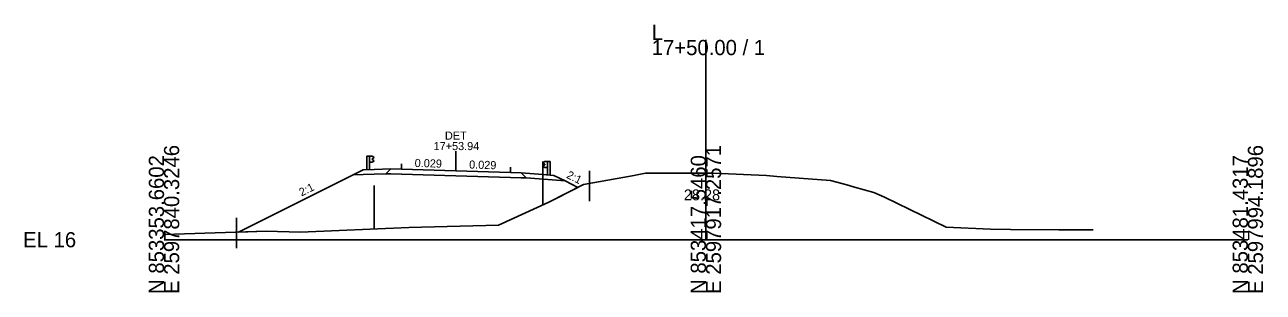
# Model space of a CAD drawing. Extents: x -26 to 1203, y -10 to 9526.
# Drawn here: x -25.7 to 202.8, y 7490.3 to 7539.7 of the extents above; entities that cross this region are included whole.
import ezdxf

# ---------------------------------------------------------------- set-up
doc = ezdxf.new("R2010")
doc.units = 0
for name, color, linetype in [('Exist Cross Section Cell', 7, 'Continuous'), ('Exist XS Center Line Elevation Label', 7, 'Continuous'), ('Exist XS Ground Line', 7, 'Continuous'), ('Prop XS Alignment Label', 7, 'Continuous'), ('Prop XS Earthwork Shape', 7, 'Continuous'), ('Prop XS EOT Tick Mark', 7, 'Continuous'), ('Prop XS Exc Vertical Line 1', 7, 'Continuous'), ('Prop XS Exc Vertical Line 2', 7, 'Continuous'), ('Prop XS Finish Grade', 7, 'Continuous'), ('Prop XS Finish Grade Earthwork', 7, 'Continuous'), ('Prop XS Finish Grade Paved Shoulder', 7, 'Continuous'), ('Prop XS Finish Grade Pavement', 7, 'Continuous'), ('Prop XS Guardrail', 7, 'Continuous'), ('Prop XS Pvmt Edge Slope', 7, 'Continuous'), ('Prop XS SE Text', 7, 'Continuous'), ('Prop XS Side Slope Text', 7, 'Continuous'), ('Prop XS Station Labels', 7, 'Continuous'), ('Prop XS Subgrade Earthwork', 7, 'Continuous'), ('Scratch_Level_1', 7, 'Continuous'), ('Scratch_Level_2', 7, 'Continuous')]:
    doc.layers.add(name, color=color, linetype=linetype)

msp = doc.modelspace()

# ---------------------------------------------------------------- linework, layer by layer
at = {"layer": 'Exist Cross Section Cell'}
for p, q in [((100, 7500), (100, 7536.86)), ((0, 7500), (100, 7500)), ((100, 7500), (200, 7500))]:
    msp.add_line(p, q, dxfattribs=at)
at = {"layer": 'Exist XS Ground Line'}
for p, q in [((86.37, 7511.81), (88.83, 7512.28)), ((88.83, 7512.28), (89.98, 7512.29)), ((89.98, 7512.29), (100.2, 7512.28)), ((100.2, 7512.28), (101.34, 7512.25)), ((101.34, 7512.25), (111.17, 7511.85)), ((71.02, 7506.9), (77.38, 7510.19)), ((77.38, 7510.19), (86.37, 7511.81)), ((111.17, 7511.85), (113.1, 7511.68)), ((113.1, 7511.68), (117.21, 7511.35)), ((117.21, 7511.35), (123.01, 7510.9)), ((123.01, 7510.9), (126.01, 7510.14)), ((126.01, 7510.14), (127.39, 7509.7)), ((127.39, 7509.7), (130.97, 7508.72)), ((130.97, 7508.72), (132.96, 7507.87)), ((132.96, 7507.87), (144.33, 7502.3)), ((61.72, 7502.71), (71.02, 7506.9)), ((0, 7500.98), (18.83, 7501.55)), ((18.83, 7501.55), (25.19, 7501.41)), ((25.19, 7501.41), (45.15, 7502.26)), ((45.15, 7502.26), (61.72, 7502.71)), ((144.33, 7502.3), (152.53, 7501.97)), ((152.53, 7501.97), (156.23, 7501.89)), ((156.23, 7501.89), (165.12, 7501.83)), ((165.12, 7501.83), (171.46, 7501.8))]:
    msp.add_line(p, q, dxfattribs=at)
at = {"layer": 'Prop XS Earthwork Shape'}
msp.add_lwpolyline([(53.87, 7511.79), (43.83, 7512.09), (41.83, 7512.15), (40.94, 7512.17), (38.76, 7512.11), (36.76, 7512.05), (34.92, 7511.99), (13.74, 7501.4), (18.83, 7501.55), (25.19, 7501.41), (45.15, 7502.26), (61.72, 7502.71), (71.02, 7506.9), (76.36, 7509.66), (74, 7510.84), (66.86, 7511.41), (65.92, 7511.44), (63.92, 7511.5)], close=True, dxfattribs=at)
at = {"layer": 'Prop XS EOT Tick Mark'}
for p, q in [((43.83, 7513.01), (43.83, 7514.01)), ((63.92, 7512.41), (63.92, 7513.41))]:
    msp.add_line(p, q, dxfattribs=at)
at = {"layer": 'Prop XS Exc Vertical Line 1'}
msp.add_line((13.38, 7504.04), (13.38, 7498.46), dxfattribs=at)
at = {"layer": 'Prop XS Exc Vertical Line 2'}
msp.add_line((78.51, 7512.73), (78.51, 7507.1), dxfattribs=at)
at = {"layer": 'Prop XS Finish Grade'}
for p, q in [((36.76, 7512.91), (34.92, 7511.99)), ((38.76, 7512.97), (36.76, 7512.91)), ((41.83, 7513.06), (38.76, 7512.97)), ((65.92, 7512.36), (69.93, 7512.03)), ((69.93, 7512.03), (71.93, 7511.87)), ((71.93, 7511.87), (74, 7510.84))]:
    msp.add_line(p, q, dxfattribs=at)
at = {"layer": 'Prop XS Finish Grade Earthwork'}
for p, q in [((34.92, 7511.99), (13.74, 7501.4)), ((74, 7510.84), (76.36, 7509.66))]:
    msp.add_line(p, q, dxfattribs=at)
at = {"layer": 'Prop XS Finish Grade Paved Shoulder'}
for p, q in [((43.83, 7513.01), (41.83, 7513.06)), ((63.92, 7512.41), (65.92, 7512.36))]:
    msp.add_line(p, q, dxfattribs=at)
at = {"layer": 'Prop XS Finish Grade Pavement'}
for p, q in [((43.83, 7513.01), (53.87, 7512.71)), ((53.87, 7512.71), (63.92, 7512.41))]:
    msp.add_line(p, q, dxfattribs=at)
at = {"layer": 'Prop XS Guardrail'}
for p, q in [((37.44, 7515.43), (37.94, 7515.43)), ((37.44, 7512.93), (37.44, 7515.43)), ((37.94, 7515.43), (38.44, 7515.43)), ((37.94, 7515.43), (37.94, 7512.93)), ((38.44, 7514.3), (37.94, 7514.3)), ((38.44, 7515.43), (38.73, 7515.23)), ((38.73, 7515.11), (38.44, 7514.91)), ((38.44, 7514.91), (38.44, 7514.82)), ((38.44, 7514.82), (38.73, 7514.62)), ((38.73, 7514.5), (38.44, 7514.3)), ((38.73, 7515.23), (38.76, 7515.17)), ((38.76, 7515.17), (38.73, 7515.11)), ((38.73, 7514.62), (38.76, 7514.56)), ((38.76, 7514.56), (38.73, 7514.5)), ((69.96, 7514.23), (69.93, 7514.17)), ((69.93, 7514.17), (69.96, 7514.11)), ((70.25, 7514.43), (69.96, 7514.23)), ((70.75, 7514.43), (70.25, 7514.43)), ((71.25, 7514.43), (70.75, 7514.43)), ((70.75, 7514.43), (70.75, 7511.93)), ((71.25, 7511.93), (71.25, 7514.43)), ((69.96, 7513.62), (69.93, 7513.56)), ((69.93, 7513.56), (69.96, 7513.5)), ((69.96, 7514.11), (70.25, 7513.91)), ((70.25, 7513.82), (69.96, 7513.62)), ((69.96, 7513.5), (70.25, 7513.3)), ((70.25, 7513.91), (70.25, 7513.82)), ((70.25, 7513.3), (70.75, 7513.3))]:
    msp.add_line(p, q, dxfattribs=at)
at = {"layer": 'Prop XS Pvmt Edge Slope'}
for p, q in [((41.83, 7513.06), (40.94, 7512.17)), ((65.92, 7512.36), (66.86, 7511.41))]:
    msp.add_line(p, q, dxfattribs=at)
at = {"layer": 'Prop XS Side Slope Text'}
msp.add_line((53.87, 7512.71), (53.87, 7516.36), dxfattribs=at)
at = {"layer": 'Prop XS Subgrade Earthwork'}
for p, q in [((36.76, 7512.05), (34.92, 7511.99)), ((38.76, 7512.11), (36.76, 7512.05)), ((40.94, 7512.17), (38.76, 7512.11)), ((41.83, 7512.15), (40.94, 7512.17)), ((43.83, 7512.09), (41.83, 7512.15)), ((53.87, 7511.79), (43.83, 7512.09)), ((63.92, 7511.5), (53.87, 7511.79)), ((63.92, 7511.5), (65.92, 7511.44)), ((65.92, 7511.44), (66.86, 7511.41)), ((66.86, 7511.41), (74, 7510.84))]:
    msp.add_line(p, q, dxfattribs=at)
at = {"layer": 'Scratch_Level_1'}
for points in [[(36.76, 7512.05), (34.92, 7511.99), (36.76, 7512.91), (38.76, 7512.97), (41.83, 7513.06), (40.94, 7512.17), (38.76, 7512.11)], [(36.76, 7512.91), (34.92, 7511.99), (36.76, 7512.05), (38.76, 7512.11), (40.94, 7512.17), (41.83, 7513.06), (38.76, 7512.97)], [(65.92, 7512.36), (69.93, 7512.03), (71.93, 7511.87), (74, 7510.84), (66.86, 7511.41)], [(66.86, 7511.41), (74, 7510.84), (71.93, 7511.87), (69.93, 7512.03), (65.92, 7512.36)]]:
    msp.add_lwpolyline(points, close=True, dxfattribs=at)
at = {"layer": 'Scratch_Level_2'}
for p, q in [((69.93, 7514.41), (69.93, 7506.41)), ((38.76, 7509.99), (38.76, 7501.99))]:
    msp.add_line(p, q, dxfattribs=at)

# ---------------------------------------------------------------- texts
at = {"layer": 'Exist Cross Section Cell'}
for s, p in [('L', (90, 7536.86)), ('17+50.00 / 1', (90, 7534.06)), ('EL 16', (-26, 7498.6))]:
    msp.add_text(s, height=2.8, dxfattribs=at).set_placement(p)
for s, p in [('E 2597840.3246', (2.8, 7490)), ('E 2597917.2571', (102.8, 7490)), ('E 2597994.1896', (202.8, 7490)), ('N 853353.6602', (0, 7490)), ('N 853417.5460', (100, 7490)), ('N 853481.4317', (200, 7490))]:
    msp.add_text(s, height=2.8, rotation=90, dxfattribs=at).set_placement(p)
at = {"layer": 'Exist XS Center Line Elevation Label'}
msp.add_text('28.28', height=2, dxfattribs=at).set_placement((95.93, 7507.28))
at = {"layer": 'Prop XS Alignment Label'}
msp.add_text('DET', height=1.5, dxfattribs=at).set_placement((51.84, 7518.46))
at = {"layer": 'Prop XS SE Text'}
for rotation, p in [(358.3148, (46.24, 7513.43)), (358.3157, (56.29, 7513.14))]:
    msp.add_text('0.029', height=1.5, rotation=rotation, dxfattribs=at).set_placement(p)
at = {"layer": 'Prop XS Side Slope Text'}
for rotation, p in [(333.4349, (74.14, 7511.46)), (26.5651, (25.38, 7507.96))]:
    msp.add_text('2:1', height=1.5, rotation=rotation, dxfattribs=at).set_placement(p)
at = {"layer": 'Prop XS Station Labels'}
msp.add_text('17+53.94', height=1.5, dxfattribs=at).set_placement((49.75, 7516.53))

doc.saveas('drawing.dxf')
